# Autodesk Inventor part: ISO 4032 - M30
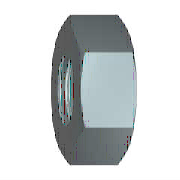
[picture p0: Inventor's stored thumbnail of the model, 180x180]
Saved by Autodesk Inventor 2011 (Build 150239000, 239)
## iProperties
IsCustomPart: 0
Created: 2010-02
Part Number: ISO 4032 - M30
Material: Stainless Steel, 440C
Description: Hex Nut
Document SubType Name: Modeling
Standard: ISO 4032
Designer: 129877
Standards Organization: DIN
Language: en-US
Size Designation: M30
Categories: <MemberInstance><Categories><Category DisplayName="Fasteners" InternalName="e4da775c-781d-43d5-af7c-5136215cf5a6" Mnemonic="FSTN"><Category DisplayName="Nuts" I
Density: 7.75 g/cm^3
Mass: 249.433 g
Surface Area: 82.479 cm^2
Volume: 32.1849 cm^3
Author: 129877
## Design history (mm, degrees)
body "Solid1"
workaxis "Work Axis1"
workplane "Work Plane1"
sketch "Sketch1"
  geometry: L1 (-26.558, 0)-(-13.279, 23); L2 (-13.279, 23)-(13.279, 23); L3 (13.279, 23)-(26.558, 0); L4 (26.558, 0)-(13.279, -23); L5 (13.279, -23)-(-13.279, -23); L6 (-13.279, -23)-(-26.558, 0); 2 further points
  constraints: 12 end point, 1 coincident, 1 horizontal, 11 other
  dimensions: "d0" = 53.11622 distance of L3.end L1.start (= 1.1547 x SW)
extrude "Body" new body sketch "Sketch1" distance "d1" = 25.6 (= KOH); taper "d2" = 0 deg
revolve "Chamfer1" stored, may be unused: angle "d7" = 90 deg
sketch "Sketch3"
  geometry: 4 further points
  constraints: 1 coincident, 1 other
hole "Thread" sketch "Sketch3" diameter "d25" = 26.211; stored, may be unused: countersink angle "d29" = 82 deg, drill point angle "d31" = 118 deg; dims "d26" = 6, "d27" = 4, "d28" = 2, "d30" = 8
chamfer "Chamfer2" distance "d8" = 1.89443 (= -0.5 x GD1 + 0.5 x NND); stored, may be unused: angle "d9" = 30 deg, second distance "d40" = 1.89443 (= -0.5 x GD1 + 0.5 x NND)
chamfer "Chamfer3" distance "d10" = 1.89443 (= -0.5 x GD1 + 0.5 x NND); stored, may be unused: angle "d11" = 30 deg, second distance "d41" = 1.89443 (= -0.5 x GD1 + 0.5 x NND)
sketch "Sketch2"
  geometry: L1 (0, 13.279)-(0, 26.558) reference; L2 (0, 26.558)-(25.6, 26.558) reference; L3 (25.6, 13.279)-(25.6, 26.558) reference; L4 (-5.12, 0)-(30.72, 0) reference; L5 (2.978, 26.558)-(0, 21.4); L6 (22.622, 26.558)-(25.6, 21.4)
  constraints: 4 end point, 4 point on line
  dimensions: "d3" = 30 deg angle of L1 L5 (= ANG1); "d4" = 30 deg angle of L3 L6 (= ANG2); "d5" = 42.8 diameter of L5.end L4 (= SW0); "d6" = 42.8 diameter of L6.end L4 (= SW01)
other parameters: "ANG1" = 30 deg [user parameter; used in 1 equation term], "ANG2" = 30 deg [user parameter; used in 1 equation term], "KOH" = 25.6 [user parameter; used in 1 equation term], "SW" = 46 [user parameter; used in 2 equation terms], "SW0" = 42.8 [user parameter; used in 1 equation term], "SW01" = 42.8 [user parameter; used in 1 equation term], "GD1" = 26.21114 (computed from THREADDIA, PTC, TOA) [user parameter; used in 4 equation terms], "d13" = 0, "d14" = 0, "d39" = 0, "d42" = 0, "GUL" = 1.89443 (= 0.541266 x PTC) [user parameter], "TPU" = 2.85714 (computed from PTC) [user parameter], "TOA" = 30 deg [user parameter; used in 1 equation term], "PTC" = 3.5 [user parameter; used in 4 equation terms], "E0" = 53.13 (= 1.155 x SW) [user parameter], "GAL" = 1.89443 (= 0.541266 x PTC) [user parameter]
